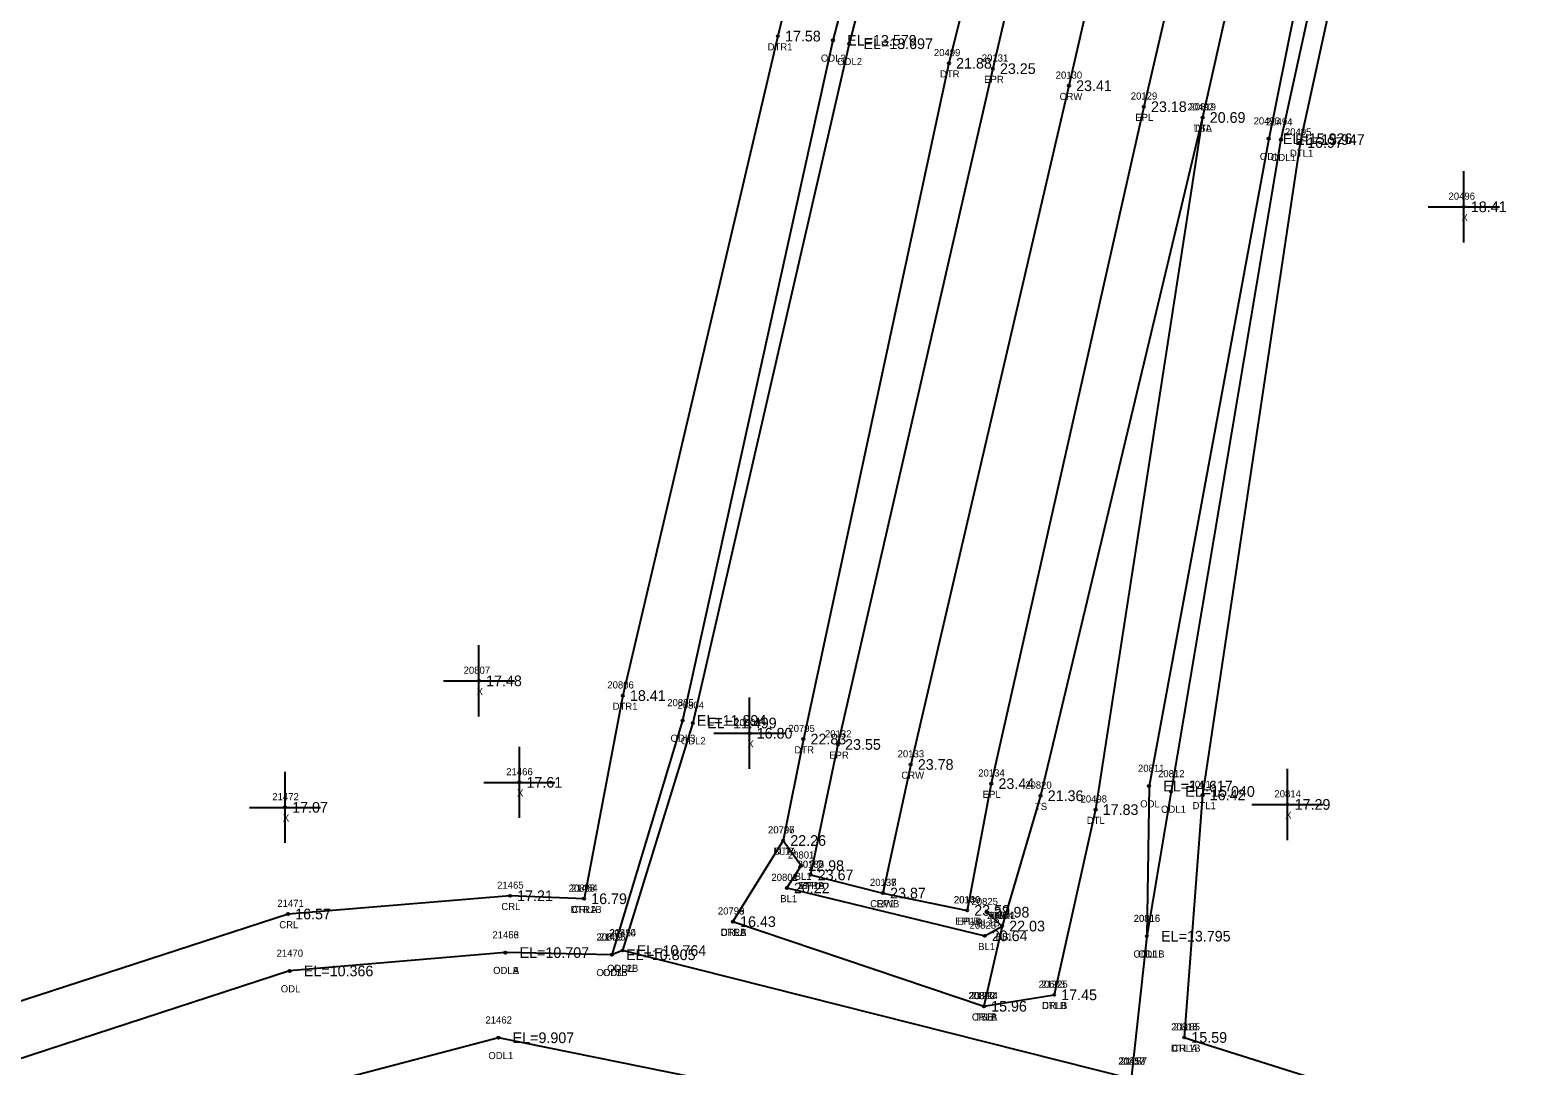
# Model space of a CAD drawing. Extents: x 2655177 to 2656219, y 761780 to 764748.
# Drawn here: x 2655601.7 to 2655813.5, y 763251.6 to 763397.1 of the extents above; entities that cross this region are included whole.
import ezdxf

# ---------------------------------------------------------------- set-up
doc = ezdxf.new("R2010")
doc.units = 0
for name, color, linetype in [('RD_DTM_BkLn1', 7, 'Continuous'), ('RD_DTM_BkLn2', 7, 'Continuous'), ('RD_DTM_BkLn_txCode', 7, 'Continuous'), ('RD_EX_H2O', 7, 'Continuous'), ('RD_EX_H2O_txCode', 7, 'Continuous'), ('RD_EX_Misc', 7, 'Continuous'), ('RD_EX_Misc_txCode', 7, 'Continuous'), ('RD_EX_Road', 7, 'Continuous'), ('RD_EX_Road_txCode', 7, 'Continuous'), ('RD_EX_TX_H2O_ELEV', 7, 'Continuous'), ('RD_EX_TX_Misc_ELEV', 7, 'Continuous'), ('RD_EX_TX_Road_ELEV', 7, 'Continuous'), ('RD_HC_Survey_ELEV', 7, 'Continuous'), ('RD_HC_Survey_txCode', 7, 'Continuous'), ('RD_SMD_Locator', 7, 'Continuous')]:
    doc.layers.add(name, color=color, linetype=linetype)

msp = doc.modelspace()

# ---------------------------------------------------------------- linework, layer by layer
at = {"layer": 'RD_DTM_BkLn1'}
for points in [[(2656052.36, 764720.46), (2656029.22, 764619.66), (2656007.41, 764523.97), (2655985.61, 764427.64), (2655963.53, 764330.64), (2655941.2, 764233.56), (2655920.06, 764141.06), (2655898.52, 764047.86), (2655877.71, 763954.88), (2655855.89, 763859.81), (2655834.07, 763763.97), (2655811.81, 763666.79), (2655790.48, 763573.22), (2655769.27, 763483.63), (2655747.64, 763389.32), (2655725.4, 763293.96), (2655721.51, 763275.9)], [(2655707.49, 763283.28), (2655710.02, 763279.75), (2655708, 763276.61), (2655735.8, 763269.89), (2655738.24, 763271.26), (2655736.06, 763273.21)]]:
    msp.add_lwpolyline(points, dxfattribs=at)
at = {"layer": 'RD_DTM_BkLn2'}
msp.add_lwpolyline([(2655766.41, 763384.86), (2655743.65, 763289.57), (2655738.24, 763271.26), (2655735.7, 763259.99)], dxfattribs=at)
at = {"layer": 'RD_EX_H2O'}
for p, q in [((2655700.44, 763271.88), (2655735.7, 763259.99)), ((2655735.7, 763259.99), (2655745.55, 763261.6))]:
    msp.add_line(p, q, dxfattribs=at)
for points in [[(2655866.2, 763781.92), (2655858.43, 763782.12), (2655853.29, 763757.63), (2655831.21, 763662.14), (2655807.21, 763570.59), (2655787.76, 763479.91), (2655766.41, 763384.86), (2655751.38, 763287.62), (2655745.55, 763261.6)], [(2655866.2, 763781.92), (2655866.81, 763773.88), (2655862.68, 763756.12), (2655841.51, 763659.39), (2655821.68, 763567.67), (2655800.98, 763476.96), (2655780.09, 763381.34), (2655766.41, 763289.68), (2655763.83, 763255.61)], [(2655859.17, 763772.66), (2655856.61, 763756.77), (2655834.86, 763661.01), (2655815.86, 763568.74), (2655795.14, 763478.35), (2655775.69, 763381.88), (2655758.88, 763290.93), (2655758.58, 763269.84), (2655756.39, 763249.8)], [(2655862.03, 763772.5), (2655859.51, 763756.17), (2655837.49, 763660.31), (2655817.79, 763568.47), (2655798.48, 763478.03), (2655777.42, 763381.75), (2655761.98, 763290.17), (2655758.58, 763269.84)], [(2655761.66, 763536.79), (2655753.68, 763542.9), (2655743.24, 763538.2), (2655729.93, 763492.02), (2655706.75, 763396.29), (2655684.97, 763303.64), (2655679.52, 763275.1)], [(2655761.66, 763536.79), (2655754.62, 763487.9), (2655730.78, 763392.48), (2655710.33, 763297.53), (2655707.49, 763283.28), (2655700.44, 763271.88)], [(2655748.84, 763534.59), (2655739.13, 763490.44), (2655714.48, 763395.7), (2655693.36, 763300.15), (2655683.42, 763267.23)], [(2655752.39, 763533.63), (2655741.17, 763489.56), (2655716.77, 763395.22), (2655694.81, 763299.79), (2655684.92, 763267.82)], [(2655679.52, 763275.1), (2655669.12, 763275.51), (2655637.94, 763272.95), (2655565.65, 763249.44), (2655503.41, 763204.6), (2655446.32, 763155.55), (2655414.68, 763121.3), (2655403.66, 763111.5), (2655354.39, 763062.15), (2655287.73, 762993.08)], [(2655756.39, 763249.8), (2655684.92, 763267.82), (2655683.42, 763267.23), (2655668.47, 763267.53), (2655668.47, 763267.53), (2655638.16, 763264.95), (2655569.96, 763242.71), (2655508.09, 763199.39), (2655452.6, 763149.1), (2655415.53, 763111.95), (2655357.86, 763058.55), (2655292.21, 762987.7)], [(2655752.5, 763238.32), (2655667.49, 763255.57), (2655638.64, 763247.96), (2655576.44, 763232.61), (2655516.78, 763189.73), (2655462.37, 763139.07), (2655430.77, 763102.29), (2655369.67, 763046.31), (2655300.53, 762977.71)], [(2655763.83, 763255.61), (2655817.49, 763238.63), (2655914.8, 763213.38), (2655950.66, 763206.21), (2656007.42, 763189.45), (2656109.25, 763159.23), (2656208.33, 763130.47)]]:
    msp.add_lwpolyline(points, dxfattribs=at)
at = {"layer": 'RD_EX_Misc'}
for p, q in [((2655803.09, 763367.31), (2655803.09, 763377.31)), ((2655798.09, 763372.31), (2655808.09, 763372.31)), ((2655664.76, 763300.71), (2655664.76, 763310.71)), ((2655659.76, 763305.71), (2655669.76, 763305.71)), ((2655702.77, 763293.35), (2655702.77, 763303.35)), ((2655697.77, 763298.35), (2655707.77, 763298.35)), ((2655670.43, 763286.45), (2655670.43, 763296.45)), ((2655637.52, 763282.94), (2655637.52, 763292.94)), ((2655778.34, 763283.35), (2655778.34, 763293.35)), ((2655665.43, 763291.45), (2655675.43, 763291.45)), ((2655773.34, 763288.35), (2655783.34, 763288.35)), ((2655632.52, 763287.94), (2655642.52, 763287.94))]:
    msp.add_line(p, q, dxfattribs=at)
at = {"layer": 'RD_EX_Road'}
for points in [[(2656041.72, 764723.31), (2656018.5, 764622.03), (2656002.75, 764552.49), (2655997.43, 764530.02), (2655974.74, 764429.64), (2655952.97, 764333.57), (2655930.52, 764235.7), (2655909.18, 764142.93), (2655887.93, 764050.57), (2655866.91, 763957.26), (2655846.82, 763869.53), (2655845.21, 763862.22), (2655839.99, 763839.71), (2655823.38, 763766.66), (2655801.33, 763669.93), (2655780.03, 763576.53), (2655774.26, 763551.85), (2655771.37, 763539.86), (2655759.09, 763486.9), (2655736.94, 763391.72), (2655715.19, 763296.77), (2655711.35, 763278.45)], [(2655930.84, 764138.62), (2655926.81, 764121.01), (2655909.26, 764045.26), (2655908.15, 764039.87), (2655902.08, 764013.51), (2655888.19, 763952.26), (2655880.73, 763919.6), (2655875, 763893.73), (2655866.73, 763857), (2655852.89, 763796.34), (2655850.73, 763786.52), (2655844.88, 763760.97), (2655822.62, 763664.7), (2655801.12, 763571.82), (2655780.32, 763481.64), (2655758.16, 763386.38), (2655736.73, 763291.27), (2655733.33, 763273.46)], [(2655711.35, 763278.45), (2655721.51, 763275.9), (2655733.33, 763273.46)]]:
    msp.add_lwpolyline(points, dxfattribs=at)
at = {"layer": 'RD_SMD_Locator'}
for centre in [(2655706.75, 763396.29), (2655714.48, 763395.7), (2655716.77, 763395.22), (2655730.78, 763392.48), (2655736.94, 763391.72), (2655747.64, 763389.32), (2655758.16, 763386.38), (2655766.41, 763384.86), (2655766.41, 763384.86), (2655775.69, 763381.88), (2655777.42, 763381.75), (2655780.09, 763381.34), (2655803.09, 763372.31), (2655664.76, 763305.71), (2655684.97, 763303.64), (2655693.36, 763300.15), (2655694.81, 763299.79), (2655702.77, 763298.35), (2655710.33, 763297.53), (2655715.19, 763296.77), (2655725.4, 763293.96), (2655670.43, 763291.45), (2655736.73, 763291.27), (2655758.88, 763290.93), (2655761.98, 763290.17), (2655637.52, 763287.94), (2655743.65, 763289.57), (2655766.41, 763289.68), (2655778.34, 763288.35), (2655751.38, 763287.62), (2655707.49, 763283.28), (2655707.49, 763283.28), (2655710.02, 763279.75), (2655711.35, 763278.45), (2655711.35, 763278.45), (2655669.12, 763275.51), (2655708, 763276.61), (2655721.51, 763275.9), (2655721.51, 763275.9), (2655679.52, 763275.1), (2655679.52, 763275.1), (2655733.33, 763273.46), (2655733.33, 763273.46), (2655736.06, 763273.21), (2655637.94, 763272.95), (2655700.44, 763271.88), (2655700.44, 763271.88), (2655738.24, 763271.26), (2655738.24, 763271.26), (2655735.8, 763269.89), (2655758.58, 763269.84), (2655758.58, 763269.84), (2655668.47, 763267.53), (2655668.47, 763267.53), (2655683.42, 763267.23), (2655683.42, 763267.23), (2655684.92, 763267.82), (2655684.92, 763267.82), (2655638.16, 763264.95), (2655745.55, 763261.6), (2655745.55, 763261.6), (2655735.7, 763259.99), (2655735.7, 763259.99), (2655735.7, 763259.99), (2655667.49, 763255.57), (2655763.83, 763255.61), (2655763.83, 763255.61)]:
    msp.add_circle(centre, 0.15, dxfattribs=at)

# ---------------------------------------------------------------- texts
at = {"layer": 'RD_DTM_BkLn_txCode'}
for s, p in [('20819', (2655764.57, 763385.86)), ('TSA', (2655765.12, 763382.86)), ('20820', (2655741.49, 763290.57)), ('TS', (2655742.86, 763287.57)), ('20797', (2655705.37, 763284.28)), ('BL1A', (2655706.08, 763281.28)), ('20801', (2655708.15, 763280.75)), ('20802', (2655705.84, 763277.61)), ('BL1', (2655709.1, 763277.75)), ('BL1', (2655707.08, 763274.61)), ('20825', (2655733.94, 763274.21)), ('20824', (2655736.12, 763272.26)), ('20821', (2655736.4, 763272.26)), ('20823', (2655733.68, 763270.89)), ('BL1B', (2655734.67, 763271.21)), ('BL1', (2655737.32, 763269.26)), ('TS', (2655737.44, 763269.26)), ('BL1', (2655734.88, 763267.89)), ('20822', (2655733.58, 763260.99)), ('TSB', (2655734.44, 763257.99))]:
    msp.add_text(s, height=1, dxfattribs=at).set_placement(p)
at = {"layer": 'RD_EX_H2O_txCode'}
for s, p in [('DTR1', (2655705.31, 763394.29)), ('20499', (2655728.66, 763393.48)), ('ODL3', (2655712.79, 763392.7)), ('ODL2', (2655715.07, 763392.22)), ('DTR', (2655729.52, 763390.48)), ('20492', (2655764.29, 763385.86)), ('DTL', (2655765.16, 763382.86)), ('20493', (2655773.57, 763383.88)), ('20494', (2655775.31, 763383.75)), ('20495', (2655777.97, 763382.34)), ('ODL', (2655774.44, 763378.88)), ('ODL1', (2655776.01, 763378.75)), ('DTL1', (2655778.68, 763379.34)), ('20806', (2655682.79, 763304.64)), ('20805', (2655691.21, 763302.15)), ('DTR1', (2655683.54, 763301.64)), ('20804', (2655692.65, 763301.79)), ('20795', (2655708.22, 763298.53)), ('ODL3', (2655691.67, 763297.15)), ('ODL2', (2655693.12, 763296.79)), ('DTR', (2655709.07, 763295.53)), ('20811', (2655757.33, 763292.93)), ('20812', (2655760.15, 763292.17)), ('20813', (2655764.58, 763290.68)), ('20498', (2655749.26, 763288.62)), ('ODL', (2655757.64, 763287.93)), ('ODL1', (2655760.57, 763287.17)), ('DTL1', (2655765, 763287.68)), ('DTL', (2655750.13, 763285.62)), ('20796', (2655705.35, 763284.28)), ('DTR', (2655706.23, 763281.28)), ('21465', (2655667.31, 763276.51)), ('20808', (2655677.36, 763276.1)), ('21464', (2655677.7, 763276.1)), ('21471', (2655636.43, 763273.95)), ('CRL', (2655667.9, 763273.51)), ('DTR1B', (2655677.62, 763273.1)), ('CRLA', (2655677.8, 763273.1)), ('20798', (2655698.32, 763272.88)), ('20799', (2655698.32, 763272.88)), ('CRL', (2655636.71, 763270.95)), ('20816', (2655756.72, 763271.84)), ('20815', (2655756.74, 763271.84)), ('21456', (2655666.65, 763269.53)), ('21463', (2655666.65, 763269.53)), ('20809', (2655681.26, 763269.23)), ('21455', (2655681.62, 763269.23)), ('20810', (2655683.05, 763269.82)), ('21454', (2655683.13, 763269.82)), ('CRLA', (2655698.73, 763269.88)), ('DTRB', (2655698.7, 763269.88)), ('21470', (2655636.33, 763266.95)), ('ODL1B', (2655756.69, 763266.84)), ('ODL', (2655757.33, 763266.84)), ('ODLA', (2655666.74, 763264.53)), ('ODLB', (2655666.75, 763264.53)), ('ODL3B', (2655681.25, 763264.23)), ('ODL', (2655682.17, 763264.23)), ('ODL2B', (2655682.76, 763264.82)), ('ODL', (2655683.68, 763264.82)), ('ODL', (2655636.92, 763261.95)), ('20603', (2655743.37, 763262.6)), ('21225', (2655743.75, 763262.6)), ('20800', (2655733.51, 763260.99)), ('21224', (2655733.91, 763260.99)), ('CRLB', (2655743.85, 763259.6)), ('DTLB', (2655743.83, 763259.6)), ('21462', (2655665.67, 763257.57)), ('CRLA', (2655733.99, 763257.99)), ('CRLB', (2655734, 763257.99)), ('20818', (2655761.99, 763256.61)), ('21185', (2655762.32, 763256.61)), ('DTL1B', (2655761.95, 763253.61)), ('CRLA', (2655762.11, 763253.61)), ('ODL1', (2655666.08, 763252.57)), ('20817', (2655754.56, 763251.8)), ('21453', (2655754.6, 763251.8)), ('21187', (2655754.88, 763251.8))]:
    msp.add_text(s, height=1, dxfattribs=at).set_placement(p)
at = {"layer": 'RD_EX_Misc_txCode'}
for s, p in [('20496', (2655800.95, 763373.31)), ('X', (2655802.78, 763370.31)), ('20807', (2655662.6, 763306.71)), ('X', (2655664.44, 763303.71)), ('20803', (2655700.61, 763299.35)), ('X', (2655702.46, 763296.35)), ('21466', (2655668.59, 763292.45)), ('X', (2655670.11, 763289.45)), ('20814', (2655776.5, 763289.35)), ('21472', (2655635.73, 763288.94)), ('X', (2655637.21, 763285.94)), ('X', (2655778.02, 763286.35))]:
    msp.add_text(s, height=1, dxfattribs=at).set_placement(p)
at = {"layer": 'RD_EX_Road_txCode'}
for s, p in [('20131', (2655735.39, 763392.72)), ('EPR', (2655735.72, 763389.72)), ('20129', (2655756.32, 763387.38)), ('EPL', (2655756.95, 763384.38)), ('20132', (2655713.36, 763297.77)), ('EPR', (2655713.96, 763294.77)), ('20134', (2655734.89, 763292.27)), ('EPL', (2655735.52, 763289.27)), ('20136', (2655709.5, 763279.45)), ('20135', (2655709.52, 763279.45)), ('EPRB', (2655709.65, 763276.45)), ('EP1A', (2655709.94, 763276.45)), ('20138', (2655719.68, 763276.9)), ('20140', (2655731.45, 763274.46)), ('20139', (2655731.49, 763274.46)), ('EP1', (2655720.59, 763273.9)), ('EPLB', (2655731.65, 763271.46)), ('EP1B', (2655731.93, 763271.46))]:
    msp.add_text(s, height=1, dxfattribs=at).set_placement(p)
at = {"layer": 'RD_EX_TX_H2O_ELEV'}
for s, p in [('17.58', (2655707.75, 763395.54)), ('EL=13.579', (2655716.48, 763394.95)), ('EL=13.697', (2655718.77, 763394.47)), ('21.88', (2655731.78, 763391.73)), ('20.69', (2655767.41, 763384.11)), ('EL=15.926', (2655777.69, 763381.13)), ('EL=15.947', (2655779.42, 763381)), ('16.97', (2655781.09, 763380.59)), ('18.41', (2655685.97, 763302.89)), ('EL=11.294', (2655695.36, 763299.4)), ('EL=11.499', (2655696.81, 763299.04)), ('22.83', (2655711.33, 763296.78)), ('EL=14.617', (2655760.88, 763290.18)), ('EL=15.040', (2655763.98, 763289.42)), ('16.42', (2655767.41, 763288.93)), ('17.83', (2655752.38, 763286.87)), ('22.26', (2655708.49, 763282.53)), ('17.21', (2655670.12, 763274.76)), ('16.79', (2655680.52, 763274.35)), ('16.79', (2655680.52, 763274.35)), ('16.57', (2655638.94, 763272.2)), ('16.43', (2655701.44, 763271.13)), ('16.43', (2655701.44, 763271.13)), ('EL=13.795', (2655760.58, 763269.09)), ('EL=13.795', (2655760.58, 763269.09)), ('EL=10.707', (2655670.47, 763266.78)), ('EL=10.707', (2655670.47, 763266.78)), ('EL=10.805', (2655685.42, 763266.48)), ('EL=10.805', (2655685.42, 763266.48)), ('EL=10.764', (2655686.92, 763267.07)), ('EL=10.764', (2655686.92, 763267.07)), ('EL=10.366', (2655640.16, 763264.2)), ('15.96', (2655736.7, 763259.24)), ('15.96', (2655736.7, 763259.24)), ('17.45', (2655746.55, 763260.85)), ('17.45', (2655746.55, 763260.85)), ('EL=9.907', (2655669.49, 763254.82)), ('15.59', (2655764.83, 763254.86)), ('15.59', (2655764.83, 763254.86))]:
    msp.add_text(s, height=1.5, dxfattribs=at).set_placement(p)
at = {"layer": 'RD_EX_TX_Misc_ELEV'}
for s, p in [('20.69', (2655767.41, 763384.11)), ('18.41', (2655804.09, 763371.56)), ('17.48', (2655665.76, 763304.96)), ('16.80', (2655703.77, 763297.6)), ('17.61', (2655671.43, 763290.7)), ('21.36', (2655744.65, 763288.82)), ('17.07', (2655638.52, 763287.19)), ('17.29', (2655779.34, 763287.6)), ('22.26', (2655708.49, 763282.53)), ('22.98', (2655711.02, 763279)), ('20.22', (2655709, 763275.86)), ('22.98', (2655737.06, 763272.46)), ('22.03', (2655739.24, 763270.51)), ('22.03', (2655739.24, 763270.51)), ('20.64', (2655736.8, 763269.14)), ('15.96', (2655736.7, 763259.24))]:
    msp.add_text(s, height=1.5, dxfattribs=at).set_placement(p)
at = {"layer": 'RD_EX_TX_Road_ELEV'}
for s, p in [('23.25', (2655737.94, 763390.97)), ('23.18', (2655759.16, 763385.63)), ('23.55', (2655716.19, 763296.02)), ('23.44', (2655737.73, 763290.52)), ('23.67', (2655712.35, 763277.7)), ('23.67', (2655712.35, 763277.7)), ('23.87', (2655722.51, 763275.15)), ('23.59', (2655734.33, 763272.71)), ('23.59', (2655734.33, 763272.71))]:
    msp.add_text(s, height=1.5, dxfattribs=at).set_placement(p)
at = {"layer": 'RD_HC_Survey_ELEV'}
for s, p in [('23.41', (2655748.64, 763388.57)), ('23.78', (2655726.4, 763293.21)), ('23.87', (2655722.51, 763275.15))]:
    msp.add_text(s, height=1.5, dxfattribs=at).set_placement(p)
at = {"layer": 'RD_HC_Survey_txCode'}
for s, p in [('20130', (2655745.77, 763390.32)), ('CRW', (2655746.32, 763387.32)), ('20133', (2655723.57, 763294.96)), ('CRW', (2655724.09, 763291.96)), ('20137', (2655719.68, 763276.9)), ('CRWB', (2655719.72, 763273.9))]:
    msp.add_text(s, height=1, dxfattribs=at).set_placement(p)

doc.saveas('drawing.dxf')
